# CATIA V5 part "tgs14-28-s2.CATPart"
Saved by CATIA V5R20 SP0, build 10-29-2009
Part number: TGS14-28-S2
Revision: 1
Definition: design
Nomenclature: TGS14-28-S2
Source: made
Description: NOT SPECIFIED
Bounding box of the stored display mesh (mm): x -22 to 0.8, y 0 to 14, z -6 to 6
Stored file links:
  C:\Users\Raffaele\Desktop\3D X SITO CF\I-MOLD\TGS-S2\tgs14-s2.step\tgs14-28-s2.CATPart
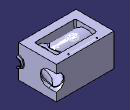
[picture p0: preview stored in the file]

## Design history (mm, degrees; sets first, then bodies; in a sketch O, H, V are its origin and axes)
Set1
  Line1 "LINE #4051": stored without definition
  DatumCurve1 "COMPOSITE_CURVE #4104"
  DatumCurve2 "COMPOSITE_CURVE #4155"
  DatumCurve3 "COMPOSITE_CURVE #4234"
  DatumCurve4 "COMPOSITE_CURVE #4277"
  DatumCurve5 "COMPOSITE_CURVE #4506"
  DatumCurve6 "COMPOSITE_CURVE #4647"
  DatumCurve7 "COMPOSITE_CURVE #4674"
  DatumCurve8 "COMPOSITE_CURVE #4732"
  DatumCurve9 "COMPOSITE_CURVE #4787"
  DatumCurve10 "COMPOSITE_CURVE #4816"
  DatumSurface1 "OPEN_SHELL #4041"
Body1 "MANIFOLD_SOLID_BREP #4042" (main body)
  Solid1: solid without history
